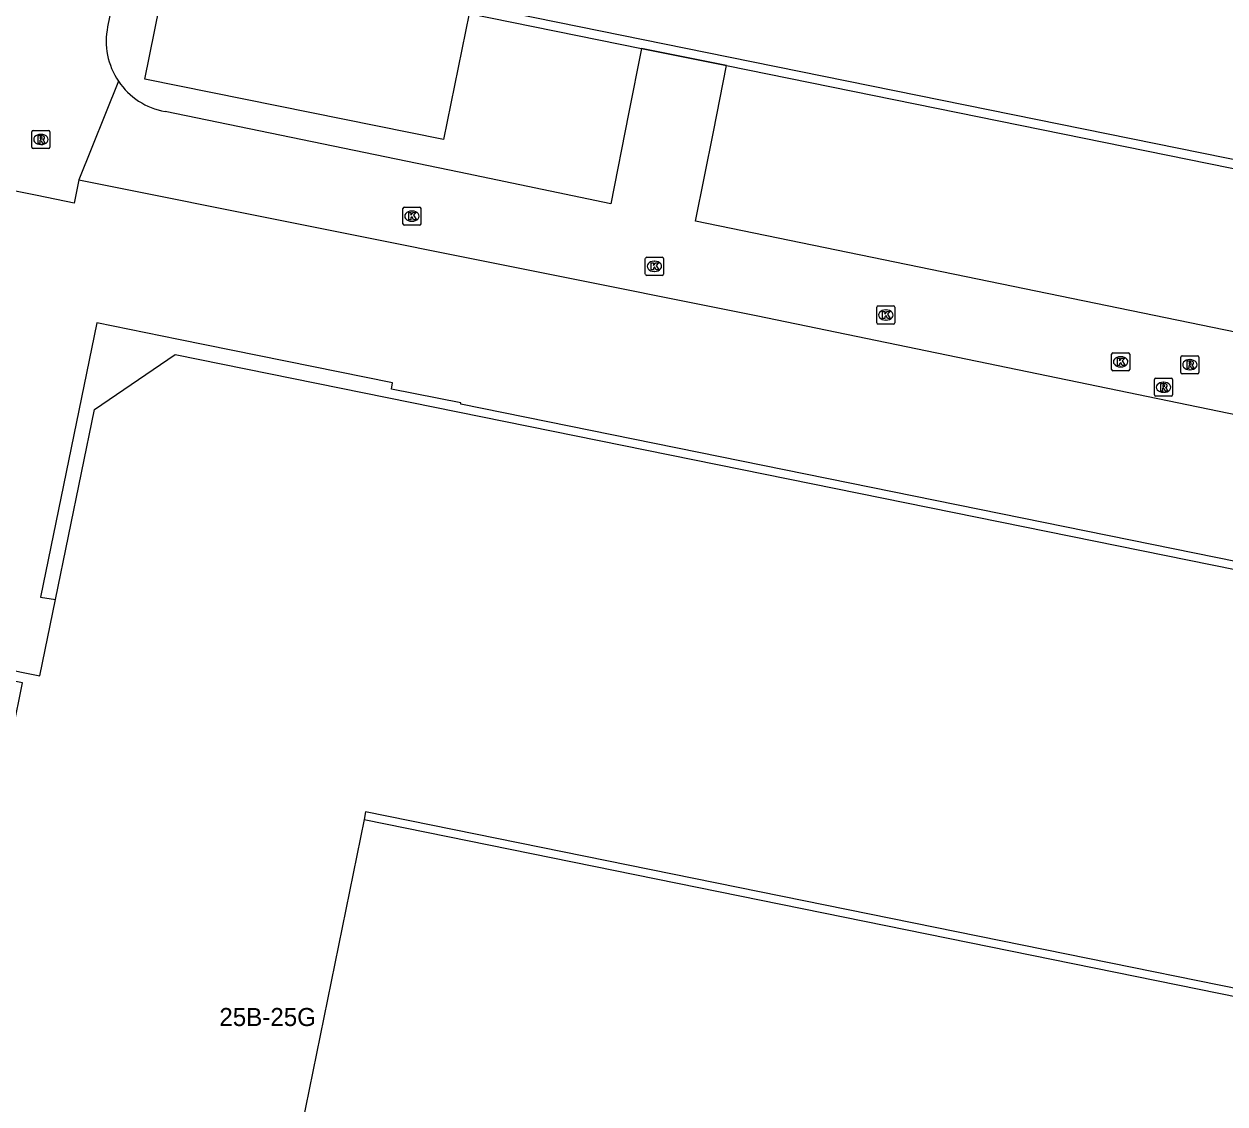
# Model space of a CAD drawing. Extents: x 157692 to 159670, y 381454 to 383289.
# Drawn here: x 158512.5 to 158579, y 381935.6 to 381995.4 of the extents above; entities that cross this region are included whole.
import ezdxf

# ---------------------------------------------------------------- set-up
doc = ezdxf.new("R2010")
doc.units = 0
for name, color, linetype in [('IMGEO_Kolk', 7, 'Continuous'), ('IMGEO_Pand', 7, 'Continuous'), ('IMGEO_Pand_nummerreeks', 7, 'Continuous'), ('IMGEO_Pand_overbouw', 7, 'Continuous'), ('IMGEO_Rijbaan_lokaal_open', 7, 'Continuous'), ('IMGEO_Rioolput', 7, 'Continuous')]:
    doc.layers.add(name, color=color, linetype=linetype)

msp = doc.modelspace()

# ---------------------------------------------------------------- linework, layer by layer
at = {"layer": 'IMGEO_Kolk'}
for p, q in [((158533.484, 381984.322), (158533.484, 381985.174)), ((158533.559, 381985.248), (158534.411, 381985.248)), ((158534.485, 381985.174), (158534.485, 381984.322)), ((158533.995, 381984.468), (158533.97, 381984.468)), ((158533.972, 381985.028), (158533.997, 381985.028)), ((158534.411, 381984.248), (158533.559, 381984.248)), ((158546.91, 381981.542), (158546.91, 381982.394)), ((158546.985, 381982.468), (158547.837, 381982.468)), ((158547.398, 381982.248), (158547.423, 381982.248)), ((158547.911, 381982.394), (158547.911, 381981.542)), ((158547.837, 381981.468), (158546.985, 381981.468)), ((158547.421, 381981.688), (158547.396, 381981.688)), ((158559.734, 381978.845), (158559.734, 381979.697)), ((158559.809, 381979.771), (158560.661, 381979.771)), ((158560.222, 381979.551), (158560.247, 381979.551)), ((158560.735, 381979.697), (158560.735, 381978.845)), ((158560.661, 381978.771), (158559.809, 381978.771)), ((158560.245, 381978.991), (158560.22, 381978.991)), ((158572.812, 381977.178), (158573.664, 381977.178)), ((158572.737, 381976.252), (158572.737, 381977.104)), ((158573.225, 381976.958), (158573.25, 381976.958)), ((158573.738, 381977.104), (158573.738, 381976.252)), ((158573.664, 381976.178), (158572.812, 381976.178)), ((158573.248, 381976.398), (158573.223, 381976.398))]:
    msp.add_line(p, q, dxfattribs=at)
for points in [[(158533.484, 381984.322), (158533.484, 381985.174)], [(158533.559, 381985.248), (158534.411, 381985.248)], [(158534.485, 381985.174), (158534.485, 381984.322)], [(158533.805, 381984.948), (158533.928, 381984.948), (158533.928, 381984.797), (158534.058, 381984.948), (158534.222, 381984.948), (158534.076, 381984.797), (158534.229, 381984.548), (158534.077, 381984.548), (158533.992, 381984.712), (158533.928, 381984.645), (158533.928, 381984.548), (158533.805, 381984.548), (158533.805, 381984.948)], [(158534.411, 381984.248), (158533.559, 381984.248)], [(158546.91, 381981.542), (158546.91, 381982.394)], [(158546.985, 381982.468), (158547.837, 381982.468)], [(158547.231, 381982.168), (158547.354, 381982.168), (158547.354, 381982.017), (158547.484, 381982.168), (158547.648, 381982.168), (158547.502, 381982.017), (158547.655, 381981.768), (158547.503, 381981.768), (158547.418, 381981.932), (158547.354, 381981.865), (158547.354, 381981.768), (158547.231, 381981.768), (158547.231, 381982.168)], [(158547.911, 381982.394), (158547.911, 381981.542)], [(158547.837, 381981.468), (158546.985, 381981.468)], [(158559.734, 381978.845), (158559.734, 381979.697)], [(158559.809, 381979.771), (158560.661, 381979.771)], [(158560.055, 381979.471), (158560.178, 381979.471), (158560.178, 381979.32), (158560.308, 381979.471), (158560.472, 381979.471), (158560.326, 381979.32), (158560.479, 381979.071), (158560.327, 381979.071), (158560.242, 381979.235), (158560.178, 381979.168), (158560.178, 381979.071), (158560.055, 381979.071), (158560.055, 381979.471)], [(158560.735, 381979.697), (158560.735, 381978.845)], [(158560.661, 381978.771), (158559.809, 381978.771)], [(158572.812, 381977.178), (158573.664, 381977.178)], [(158572.737, 381976.252), (158572.737, 381977.104)], [(158573.058, 381976.878), (158573.181, 381976.878), (158573.181, 381976.727), (158573.311, 381976.878), (158573.475, 381976.878), (158573.329, 381976.727), (158573.482, 381976.478), (158573.33, 381976.478), (158573.245, 381976.642), (158573.181, 381976.575), (158573.181, 381976.478), (158573.058, 381976.478), (158573.058, 381976.878)], [(158573.738, 381977.104), (158573.738, 381976.252)], [(158573.664, 381976.178), (158572.812, 381976.178)]]:
    msp.add_lwpolyline(points, dxfattribs=at)
for centre, start, end in [((158533.561, 381985.172), 91.55205, 178.44795), ((158533.561, 381985.172), 91.55205, 178.44795), ((158534.409, 381985.172), 1.55205, 88.44795), ((158534.409, 381985.172), 1.55205, 88.44795), ((158533.561, 381984.324), 181.55205, 268.44795), ((158533.561, 381984.324), 181.55205, 268.44795), ((158534.409, 381984.324), 271.55205, 358.44795), ((158534.409, 381984.324), 271.55205, 358.44795), ((158546.987, 381982.392), 91.55205, 178.44795), ((158546.987, 381982.392), 91.55205, 178.44795), ((158547.835, 381982.392), 1.55205, 88.44795), ((158547.835, 381982.392), 1.55205, 88.44795), ((158546.987, 381981.544), 181.55205, 268.44795), ((158546.987, 381981.544), 181.55205, 268.44795), ((158547.835, 381981.544), 271.55205, 358.44795), ((158547.835, 381981.544), 271.55205, 358.44795), ((158559.811, 381979.695), 91.55205, 178.44795), ((158559.811, 381979.695), 91.55205, 178.44795), ((158560.659, 381979.695), 1.55205, 88.44795), ((158560.659, 381979.695), 1.55205, 88.44795), ((158559.811, 381978.847), 181.55205, 268.44795), ((158559.811, 381978.847), 181.55205, 268.44795), ((158560.659, 381978.847), 271.55205, 358.44795), ((158560.659, 381978.847), 271.55205, 358.44795), ((158572.814, 381977.102), 91.55205, 178.44795), ((158572.814, 381977.102), 91.55205, 178.44795), ((158573.662, 381977.102), 1.55205, 88.44795), ((158573.662, 381977.102), 1.55205, 88.44795), ((158572.814, 381976.254), 181.55205, 268.44795), ((158572.814, 381976.254), 181.55205, 268.44795), ((158573.662, 381976.254), 271.55205, 358.44795), ((158573.662, 381976.254), 271.55205, 358.44795)]:
    msp.add_arc(centre, 0.0765, start, end, dxfattribs=at)
for centre, major_axis, ratio, start_param, end_param in [((158533.971, 381984.748), (-0.387, 0.002), 0.722429, 4.712389, 7.853982), ((158533.996, 381984.748), (-0.39, 0.002), 0.717154, 1.570796, 4.712389), ((158547.397, 381981.968), (-0.387, 0.002), 0.722429, 4.712389, 7.853982), ((158547.422, 381981.968), (-0.39, 0.002), 0.717154, 1.570796, 4.712389), ((158560.221, 381979.271), (-0.387, 0.002), 0.722429, 4.712389, 7.853982), ((158560.246, 381979.271), (-0.39, 0.002), 0.717154, 1.570796, 4.712389), ((158573.224, 381976.678), (-0.387, 0.002), 0.722429, 4.712389, 7.853982), ((158573.249, 381976.678), (-0.39, 0.002), 0.717154, 1.570796, 4.712389)]:
    msp.add_ellipse(centre, major_axis=major_axis, ratio=ratio, start_param=start_param, end_param=end_param, dxfattribs=at)
at = {"layer": 'IMGEO_Pand'}
for points in [[(158628.896, 381977.861), (158551.508, 381993.562), (158546.79, 381994.52), (158537.238, 381996.458), (158537.162, 381995.98), (158535.731, 381988.998), (158519.182, 381992.341), (158521.352, 382003.003), (158519.908, 382003.291), (158520.013, 382003.834), (158522.34, 382003.369), (158523.175, 382007.551), (158523.336, 382008.252), (158526.141, 382021.958), (158633.426, 382000.171), (158628.896, 381977.861)], [(158508.319, 381934.557), (158510.851, 381946.814), (158511.114, 381948.085), (158510.249, 381948.266), (158512.421, 381958.9), (158510.945, 381959.2), (158511.057, 381959.748), (158513.377, 381959.289), (158514.237, 381963.509), (158516.406, 381974.043), (158520.877, 381977.084), (158631.822, 381954.576), (158628.775, 381939.629), (158627.277, 381932.282)], [(158619.967, 381933.766), (158531.41, 381951.745), (158531.337, 381951.328), (158527.076, 381930.395)]]:
    msp.add_lwpolyline(points, dxfattribs=at)
at = {"layer": 'IMGEO_Pand_overbouw'}
for points in [[(158537.162, 381995.98), (158546.696, 381994.043), (158551.412, 381993.084), (158629.29, 381977.261), (158634.018, 382000.555), (158541.821, 382019.31), (158541.878, 382019.607), (158525.478, 382022.916), (158522.548, 382008.404), (158522.41, 382007.723), (158523.175, 382007.551), (158523.336, 382008.252), (158526.141, 382021.958), (158633.426, 382000.171), (158628.896, 381977.861), (158551.508, 381993.562), (158546.79, 381994.52), (158537.238, 381996.458)], [(158516.406, 381974.043), (158520.877, 381977.084), (158631.822, 381954.576), (158628.775, 381939.629), (158627.277, 381932.282), (158623.887, 381932.97), (158619.967, 381933.766), (158531.41, 381951.745), (158531.337, 381951.328), (158620.295, 381933.25), (158627.613, 381931.763), (158629.113, 381939.129), (158632.326, 381954.913), (158536.7, 381974.336), (158536.694, 381974.403), (158532.847, 381975.17), (158532.905, 381975.511), (158521.046, 381977.918), (158516.525, 381978.835), (158513.404, 381963.633), (158514.237, 381963.509)]]:
    msp.add_lwpolyline(points, close=True, dxfattribs=at)
at = {"layer": 'IMGEO_Rijbaan_lokaal_open'}
for points in [[(158515.538, 381986.757), (158515.269, 381985.459), (158513.218, 381985.883), (158511.57, 381986.217), (158509.677, 381986.614), (158509.827, 381987.329), (158509.408, 381987.417), (158515.877, 382018.987), (158516.515, 382022.182)], [(158519.648, 382018.983), (158521.903, 382018.543), (158518.946, 382004.082), (158517.13, 381995.243)], [(158634.147, 381967.084), (158633.167, 381967.299), (158602.775, 381973.547), (158597.231, 381974.687), (158590.704, 381976.029), (158549.681, 381984.468), (158550.677, 381989.427), (158551.412, 381993.084), (158546.696, 381994.043), (158545.983, 381990.412), (158545.003, 381985.431), (158536.606, 381987.176), (158520.308, 381990.539)], [(158517.727, 381992.221), (158515.538, 381986.757)], [(158515.538, 381986.757), (158553.046, 381979.24), (158589.775, 381971.664), (158632.151, 381962.924), (158633.149, 381962.709)]]:
    msp.add_lwpolyline(points, dxfattribs=at)
for centre, radius, start, end in [((158521.013, 381994.44), 3.965, 168.31943, 214.03049), ((158521.01, 381994.438), 3.961, 214.02493, 259.79167)]:
    msp.add_arc(centre, radius, start, end, dxfattribs=at)
at = {"layer": 'IMGEO_Rioolput'}
for p, q in [((158512.933, 381988.569), (158512.933, 381989.421)), ((158513.008, 381989.495), (158513.86, 381989.495)), ((158513.421, 381989.275), (158513.446, 381989.275)), ((158513.934, 381989.421), (158513.934, 381988.569)), ((158513.86, 381988.495), (158513.008, 381988.495)), ((158513.444, 381988.715), (158513.419, 381988.715)), ((158576.573, 381976.092), (158576.573, 381976.944)), ((158576.648, 381977.018), (158577.5, 381977.018)), ((158577.061, 381976.798), (158577.086, 381976.798)), ((158577.574, 381976.944), (158577.574, 381976.092)), ((158577.5, 381976.018), (158576.648, 381976.018)), ((158577.084, 381976.238), (158577.059, 381976.238)), ((158575.113, 381974.842), (158575.113, 381975.694)), ((158575.188, 381975.768), (158576.04, 381975.768)), ((158575.601, 381975.548), (158575.626, 381975.548)), ((158576.114, 381975.694), (158576.114, 381974.842)), ((158576.04, 381974.768), (158575.188, 381974.768)), ((158575.624, 381974.988), (158575.599, 381974.988))]:
    msp.add_line(p, q, dxfattribs=at)
for points in [[(158512.933, 381988.569), (158512.933, 381989.421)], [(158513.008, 381989.495), (158513.86, 381989.495)], [(158513.522, 381989.193), (158513.27, 381989.195), (158513.27, 381988.795)], [(158513.934, 381989.421), (158513.934, 381988.569)], [(158513.86, 381988.495), (158513.008, 381988.495)], [(158513.27, 381988.795), (158513.394, 381988.795), (158513.394, 381988.957), (158513.405, 381988.957)], [(158513.448, 381989.114), (158513.394, 381989.114), (158513.394, 381989.033)], [(158513.394, 381989.033), (158513.446, 381989.033)], [(158513.452, 381988.928), (158513.523, 381988.795), (158513.663, 381988.795), (158513.598, 381988.921)], [(158576.573, 381976.092), (158576.573, 381976.944)], [(158576.648, 381977.018), (158577.5, 381977.018)], [(158577.162, 381976.716), (158576.91, 381976.718), (158576.91, 381976.318)], [(158577.088, 381976.637), (158577.034, 381976.637), (158577.034, 381976.556)], [(158577.034, 381976.556), (158577.086, 381976.556)], [(158577.574, 381976.944), (158577.574, 381976.092)], [(158577.5, 381976.018), (158576.648, 381976.018)], [(158576.91, 381976.318), (158577.034, 381976.318), (158577.034, 381976.48), (158577.045, 381976.48)], [(158577.092, 381976.451), (158577.163, 381976.318), (158577.303, 381976.318), (158577.238, 381976.444)], [(158575.113, 381974.842), (158575.113, 381975.694)], [(158575.188, 381975.768), (158576.04, 381975.768)], [(158575.702, 381975.466), (158575.45, 381975.468), (158575.45, 381975.068)], [(158575.45, 381975.068), (158575.574, 381975.068), (158575.574, 381975.23), (158575.585, 381975.23)], [(158575.628, 381975.387), (158575.574, 381975.387), (158575.574, 381975.306)], [(158575.574, 381975.306), (158575.626, 381975.306)], [(158575.632, 381975.201), (158575.703, 381975.068), (158575.843, 381975.068), (158575.778, 381975.194)], [(158576.114, 381975.694), (158576.114, 381974.842)], [(158576.04, 381974.768), (158575.188, 381974.768)]]:
    msp.add_lwpolyline(points, dxfattribs=at)
for centre, radius, start, end in [((158513.01, 381989.419), 0.0765, 91.55205, 178.44795), ((158513.01, 381989.419), 0.0765, 91.55205, 178.44795), ((158513.521, 381989.083), 0.109, 350.36119, 89.41601), ((158513.858, 381989.419), 0.0765, 1.55205, 88.44795), ((158513.858, 381989.419), 0.0765, 1.55205, 88.44795), ((158513.01, 381988.571), 0.0765, 181.55205, 268.44795), ((158513.01, 381988.571), 0.0765, 181.55205, 268.44795), ((158513.404, 381988.904), 0.0533, 26.02933, 88.69889), ((158513.43, 381989.222), 0.19, 274.7715, 282.96867), ((158513.454, 381989.018), 0.0964, 77.00612, 93.18647), ((158513.468, 381989.075), 0.0378, 276.66336, 79.67722), ((158513.519, 381989.083), 0.112, 277.58423, 350.98172), ((158513.503, 381988.868), 0.108, 29.51342, 73.79051), ((158513.858, 381988.571), 0.0765, 271.55205, 358.44795), ((158513.858, 381988.571), 0.0765, 271.55205, 358.44795), ((158576.65, 381976.942), 0.0765, 91.55205, 178.44795), ((158576.65, 381976.942), 0.0765, 91.55205, 178.44795), ((158577.07, 381976.745), 0.19, 274.7715, 282.96867), ((158577.094, 381976.541), 0.0964, 77.00612, 93.18647), ((158577.108, 381976.598), 0.0378, 276.66336, 79.67722), ((158577.161, 381976.606), 0.109, 350.36119, 89.41601), ((158577.159, 381976.606), 0.112, 277.58423, 350.98172), ((158577.143, 381976.391), 0.108, 29.51342, 73.79051), ((158577.498, 381976.942), 0.0765, 1.55205, 88.44795), ((158577.498, 381976.942), 0.0765, 1.55205, 88.44795), ((158576.65, 381976.094), 0.0765, 181.55205, 268.44795), ((158576.65, 381976.094), 0.0765, 181.55205, 268.44795), ((158577.044, 381976.427), 0.0533, 26.02933, 88.69889), ((158577.498, 381976.094), 0.0765, 271.55205, 358.44795), ((158577.498, 381976.094), 0.0765, 271.55205, 358.44795), ((158575.19, 381975.692), 0.0765, 91.55205, 178.44795), ((158575.19, 381975.692), 0.0765, 91.55205, 178.44795), ((158575.584, 381975.177), 0.0533, 26.02933, 88.69889), ((158575.61, 381975.495), 0.19, 274.7715, 282.96867), ((158575.634, 381975.291), 0.0964, 77.00612, 93.18647), ((158575.648, 381975.348), 0.0378, 276.66336, 79.67722), ((158575.701, 381975.356), 0.109, 350.36119, 89.41601), ((158575.699, 381975.356), 0.112, 277.58423, 350.98172), ((158575.683, 381975.141), 0.108, 29.51342, 73.79051), ((158576.038, 381975.692), 0.0765, 1.55205, 88.44795), ((158576.038, 381975.692), 0.0765, 1.55205, 88.44795), ((158575.19, 381974.844), 0.0765, 181.55205, 268.44795), ((158575.19, 381974.844), 0.0765, 181.55205, 268.44795), ((158576.038, 381974.844), 0.0765, 271.55205, 358.44795), ((158576.038, 381974.844), 0.0765, 271.55205, 358.44795)]:
    msp.add_arc(centre, radius, start, end, dxfattribs=at)
for centre, major_axis, ratio, start_param, end_param in [((158513.42, 381988.995), (-0.387, 0.002), 0.722429, 4.712389, 7.853982), ((158513.445, 381988.995), (-0.39, 0.002), 0.717154, 1.570796, 4.712389), ((158577.06, 381976.518), (-0.387, 0.002), 0.722429, 4.712389, 7.853982), ((158577.085, 381976.518), (-0.39, 0.002), 0.717154, 1.570796, 4.712389), ((158575.6, 381975.268), (-0.387, 0.002), 0.722429, 4.712389, 7.853982), ((158575.625, 381975.268), (-0.39, 0.002), 0.717154, 1.570796, 4.712389)]:
    msp.add_ellipse(centre, major_axis=major_axis, ratio=ratio, start_param=start_param, end_param=end_param, dxfattribs=at)

# ---------------------------------------------------------------- texts
at = {"layer": 'IMGEO_Pand_nummerreeks'}
msp.add_text('25B-25G', height=1, dxfattribs=at).set_placement((158523.315, 381939.885))

doc.saveas('drawing.dxf')
